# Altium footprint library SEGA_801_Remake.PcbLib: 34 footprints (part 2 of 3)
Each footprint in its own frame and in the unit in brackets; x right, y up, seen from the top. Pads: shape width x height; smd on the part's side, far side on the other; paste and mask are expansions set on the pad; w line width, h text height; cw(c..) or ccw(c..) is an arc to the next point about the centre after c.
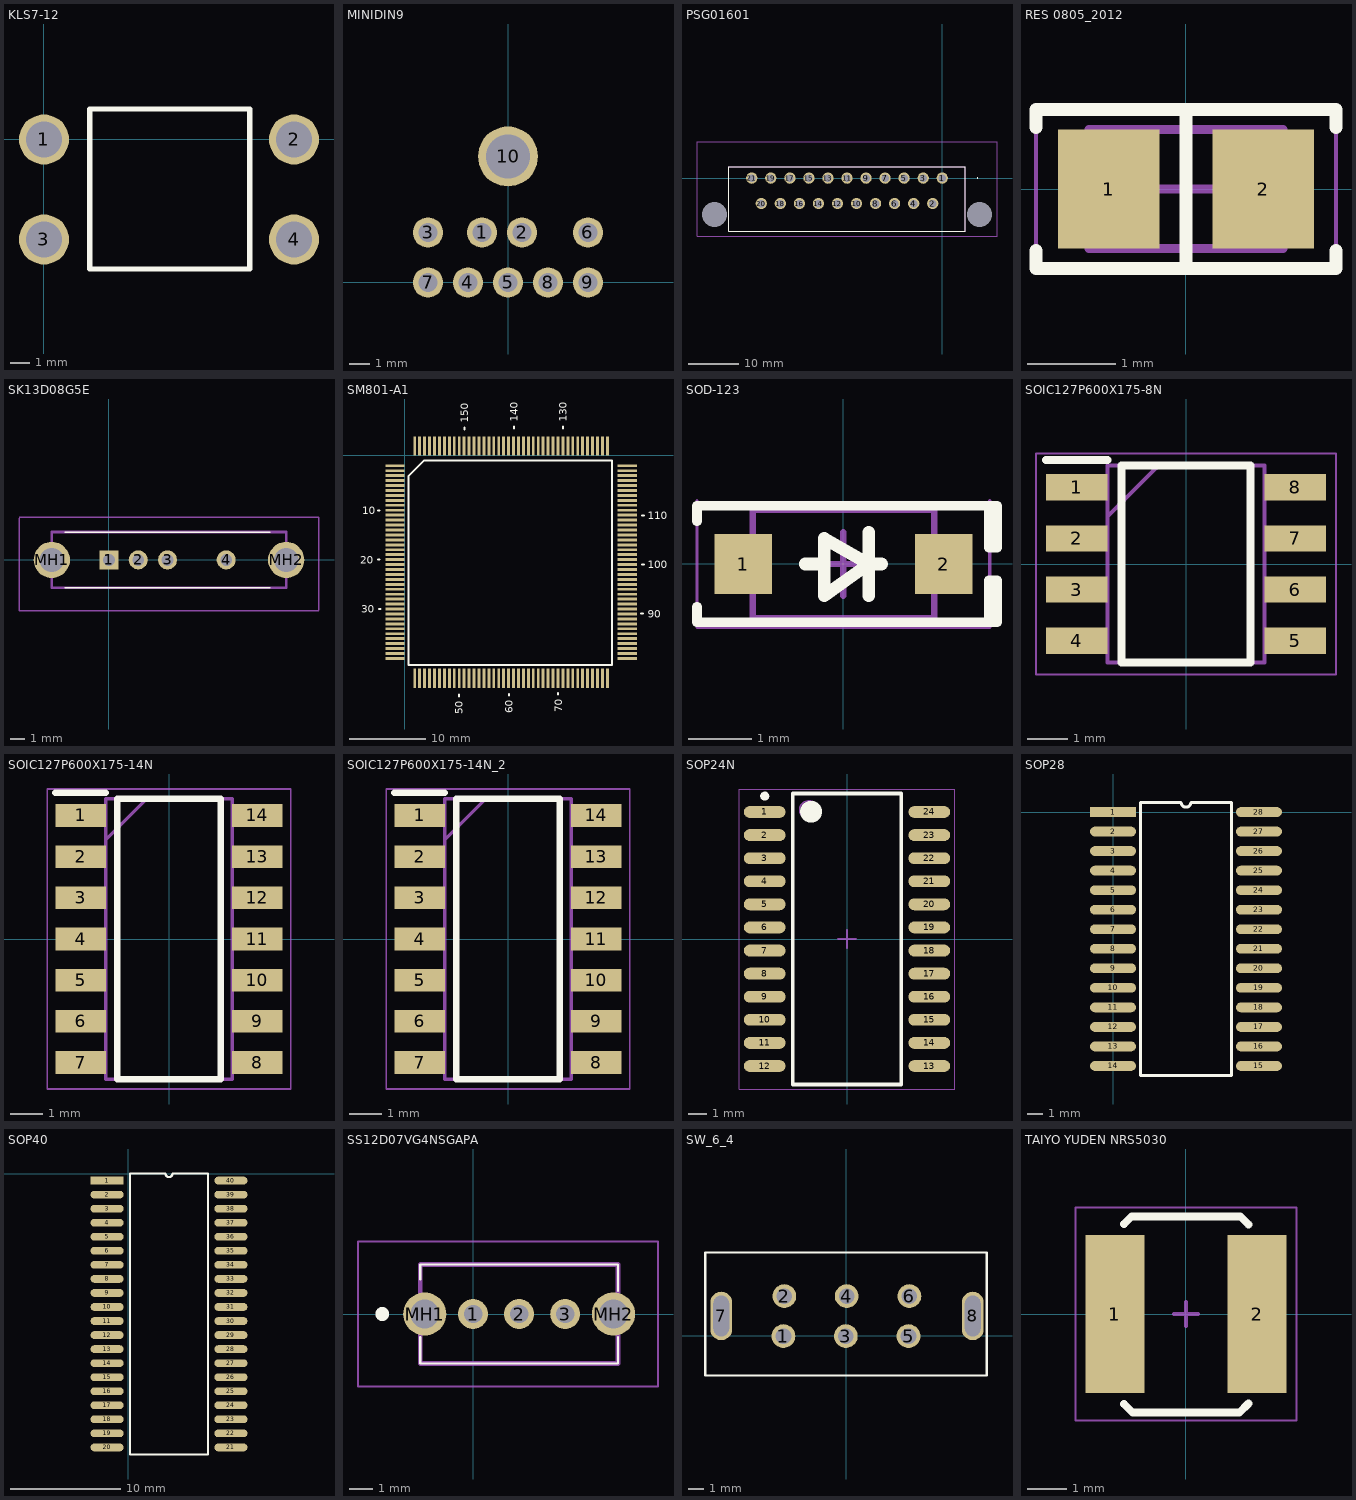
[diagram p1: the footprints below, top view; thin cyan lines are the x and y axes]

## KLS7-12 [mm]
pads (4):
  round 2.5 hole 1.8: 1(0,0) 2(12.5,0) 3(0,-5) 4(12.5,-5)
Top Overlay:
  lines w0.254: 2.286,-6.477 2.286,1.524 10.287,1.524 10.287,-6.477 2.286,-6.477

## MINIDIN9 [mm]
pads (10):
  round 1.524 hole 0.95: 1(-1.3,2.5) 2(0.7,2.5) 3(-4,2.5) 4(-2,0) 5(0,0) 6(4,2.5) 7(-4,0) 8(2,0) 9(4,0)
  round 3 hole 2.2: 10(0,6.3)
Bottom Overlay:
  lines w0.254: -7.5,-1.651 7.5,-1.651 7.5,11 -7.5,11 -7.5,-1.651

## PSG01601 [mm]
pads (23):
  round 2.25 hole 1.5: 1(0,0) 2(-1.905,-5.08) 3(-3.81,0) 4(-5.715,-5.08) 5(-7.62,0) 6(-9.525,-5.08) 7(-11.43,0) 8(-13.335,-5.08) 9(-15.24,0) 10(-17.145,-5.08) 11(-19.05,0) 12(-20.955,-5.08) 13(-22.86,0) 14(-24.765,-5.08) 15(-26.67,0) 16(-28.575,-5.08) 17(-30.48,0) 18(-32.385,-5.08) 19(-34.29,0) 20(-36.195,-5.08) 21(-38.1,0)
  round 2.5 hole 5 unplated: MH1(-45.55,-7.28) MH2(7.45,-7.28)
Top Overlay:
  lines w0.1: 7,0 cw(c7.05,0) 7.1,0 cw(c7.05,0) 7,0
  lines w0.2: -42.65,-10.6 -42.65,2.286 -26.886,2.286 -11.214,2.286 4.55,2.286 4.55,-10.6 -42.65,-10.6
Mechanical 13:
  lines w0.1: -42.65,-10.6 -42.65,2.286 -26.886,2.286 -11.214,2.286 -6.94,2.286 4.24,2.286 4.55,2.286 4.55,-10.6 -42.65,-10.6
Mechanical 15:
  lines w0.1: -49.05,-11.6 -49.05,7.25 10.95,7.25 10.95,-11.6 -49.05,-11.6
3D body "PSG01601.stp": height 16.8, standoff -5, extent -47.814,-14.31 9.968,2.54

## RES 0805_2012 [mm] "Chip Resistor, 2-Leads, Body 2.00x1.25mm, IPC Medium Density"
height 0.7
pads (2):
  rect 1.15x1.35 smd: 1(-0.875,0) 2(0.875,0)
Top Overlay:
  lines w0.15: -1.7,-0.7 -1.7,-0.9 1.7,-0.9 1.7,-0.7 ; -1.7,0.7 -1.7,0.9 1.7,0.9 1.7,0.7 ; 0,-0.9 0,0.9
Mechanical 13:
  lines w0.1: -1.1,-0.675 1.1,-0.675 1.1,0.675 -1.1,0.675 -1.1,-0.675
Mechanical 15:
  lines w0.05: -1.7,-0.95 1.7,-0.95 1.7,0.95 -1.7,0.95 -1.7,-0.95
  lines w0.1: -0.5,0 0.5,0 ; 0,-0.5 0,0.5
3D body "0805 resistor.STEP": height 0.6, standoff 0, extent -1,-0.625 1,0.625

## SK13D08G5E [mm]
pads (6):
  rect 1.3x1.3 hole 0.8: 1(0,0)
  round 1.3 hole 0.8: 2(2,0) 3(4,0) 4(8,0)
  round 2.475 hole 1.65: MH1(-3.9,0) MH2(12.1,0)
Top Overlay:
  lines w0.1: -3,-1.9 11,-1.9 ; -3,1.9 11,1.9
Mechanical 13:
  lines w0.2: -3.9,-1.9 -3.9,1.9 12.1,1.9 12.1,-1.9 -3.9,-1.9
Mechanical 15:
  lines w0.1: -6.137,2.9 14.337,2.9 14.337,-3.429 ; -6.123,2.847 -6.123,-3.455 -1.019,-3.455 9.218,-3.455 14.337,-3.455

## SM801-A1 [mil]
pads (160):
  rect 100x15 smd: 1(-50.75,-53.45) 2(-50.75,-79.05) 3(-50.75,-104.65) 4(-50.75,-130.25) 5(-50.75,-155.85) 6(-50.75,-181.45) 7(-50.75,-207.05) 8(-50.75,-232.65) 9(-50.75,-258.25) 10(-50.75,-283.85) 11(-50.75,-309.45) 12(-50.75,-335.05) 13(-50.75,-360.65) 14(-50.75,-386.25) 15(-50.75,-411.85) 16(-50.75,-437.45) 17(-50.75,-463.05) 18(-50.75,-488.65) 19(-50.75,-514.25) 20(-50.75,-539.85) 21(-50.75,-565.45) 22(-50.75,-591.05) 23(-50.75,-616.65) 24(-50.75,-642.25) 25(-50.75,-667.85) 26(-50.75,-693.45) 27(-50.75,-719.05) 28(-50.75,-744.65) 29(-50.75,-770.25) 30(-50.75,-795.85) 31(-50.75,-821.45) 32(-50.75,-847.05) 33(-50.75,-872.65) 34(-50.75,-898.25) 35(-50.75,-923.85) 36(-50.75,-949.45) 37(-50.75,-975.05) 38(-50.75,-1000.65) 39(-50.75,-1026.25) 40(-50.75,-1051.85) 81(1152.45,-1051.85) 82(1152.45,-1026.25) 83(1152.45,-1000.65) 84(1152.45,-975.05) 85(1152.45,-949.45) 86(1152.45,-923.85) 87(1152.45,-898.25) 88(1152.45,-872.65) 89(1152.45,-847.05) 90(1152.45,-821.45) 91(1152.45,-795.85) 92(1152.45,-770.25) 93(1152.45,-744.65) 94(1152.45,-719.05) 95(1152.45,-693.45) 96(1152.45,-667.85) 97(1152.45,-642.25) 98(1152.45,-616.65) 99(1152.45,-591.05) 100(1152.45,-565.45) 101(1152.45,-539.85) 102(1152.45,-514.25) 103(1152.45,-488.65) 104(1152.45,-463.05) 105(1152.45,-437.45) 106(1152.45,-411.85) 107(1152.45,-386.25) 108(1152.45,-360.65) 109(1152.45,-335.05) 110(1152.45,-309.45) 111(1152.45,-283.85) 112(1152.45,-258.25) 113(1152.45,-232.65) 114(1152.45,-207.05) 115(1152.45,-181.45) 116(1152.45,-155.85) 117(1152.45,-130.25) 118(1152.45,-104.65) 119(1152.45,-79.05) 120(1152.45,-53.45)
  rect 15x100 smd: 41(51.65,-1154.25) 42(77.25,-1154.25) 43(102.85,-1154.25) 44(128.45,-1154.25) 45(154.05,-1154.25) 46(179.65,-1154.25) 47(205.25,-1154.25) 48(230.85,-1154.25) 49(256.45,-1154.25) 50(282.05,-1154.25) 51(307.65,-1154.25) 52(333.25,-1154.25) 53(358.85,-1154.25) 54(384.45,-1154.25) 55(410.05,-1154.25) 56(435.65,-1154.25) 57(461.25,-1154.25) 58(486.85,-1154.25) 59(512.45,-1154.25) 60(538.05,-1154.25) 61(563.65,-1154.25) 62(589.25,-1154.25) 63(614.85,-1154.25) 64(640.45,-1154.25) 65(666.05,-1154.25) 66(691.65,-1154.25) 67(717.25,-1154.25) 68(742.85,-1154.25) 69(768.45,-1154.25) 70(794.05,-1154.25) 71(819.65,-1154.25) 72(845.25,-1154.25) 73(870.85,-1154.25) 74(896.45,-1154.25) 75(922.05,-1154.25) 76(947.65,-1154.25) 77(973.25,-1154.25) 78(998.85,-1154.25) 79(1024.45,-1154.25) 80(1050.05,-1154.25) 121(1050.05,48.95) 122(1024.45,48.95) 123(998.85,48.95) 124(973.25,48.95) 125(947.65,48.95) 126(922.05,48.95) 127(896.45,48.95) 128(870.85,48.95) 129(845.25,48.95) 130(819.65,48.95) 131(794.05,48.95) 132(768.45,48.95) 133(742.85,48.95) 134(717.25,48.95) 135(691.65,48.95) 136(666.05,48.95) 137(640.45,48.95) 138(614.85,48.95) 139(589.25,48.95) 140(563.65,48.95) 141(538.05,48.95) 142(512.45,48.95) 143(486.85,48.95) 144(461.25,48.95) 145(435.65,48.95) 146(410.05,48.95) 147(384.45,48.95) 148(358.85,48.95) 149(333.25,48.95) 150(307.65,48.95) 151(282.05,48.95) 152(256.45,48.95) 153(230.85,48.95) 154(205.25,48.95) 155(179.65,48.95) 156(154.05,48.95) 157(128.45,48.95) 158(102.85,48.95) 159(77.25,48.95) 160(51.65,48.95)
Top Overlay:
  lines w10: -140,-540 -130,-540 ; -140,-285 -130,-285 ; -135,-795 -125,-795 ; 280,-1250 280,-1240 ; 310,135 310,145 ; 540,-1245 540,-1235 ; 565,140 565,150 ; 795,-1240 795,-1230 ; 820,140 820,150 ; 1225,-820 1235,-820 ; 1230,-565 1240,-565 ; 1230,-310 1240,-310 ; 20,-1085 20,-105 100,-25 1075,-25 1075,-1085 20,-1085
  text "150" at 330,170 h40
  text "140" at 585,175 h40
  text "130" at 840,175 h40
  text "110" at 1260,-330 h40
  text "100" at 1260,-585 h40
  text "90" at 1260,-840 h40
  text "70" at 815,-1330 h40
  text "60" at 560,-1335 h40
  text "50" at 300,-1340 h40
  text "30" at -225,-815 h40
  text "20" at -230,-560 h40
  text "10" at -220,-305 h40

## SOD-123 [mm] "SOD, 2-Leads, Body 1.55x3.70mm, IPC Medium Density"
height 1.35
pads (2):
  rect 0.9x0.95 smd: 1(-1.575,0) 2(1.575,0)
Top Overlay:
  lines w0.15: -2.3,-0.675 -2.3,-0.916 2.286,-0.916 ; -2.3,0.675 -2.3,0.916 2.286,0.916 ; 2.286,-0.916 2.286,-0.254 2.413,-0.254 2.413,-0.916 2.286,-0.916 ; 2.286,0.916 2.413,0.916 2.413,0.254 2.286,0.254 2.286,0.916
  lines w0.2: -0.6,0 -0.3,0 ; 0.4,-0.5 0.4,0.5 ; 0.6,0 0.4,0 ; 0.4,0 -0.3,-0.5 -0.3,0.4 0.4,0
Mechanical 13:
  lines w0.1: -1.425,-0.85 1.425,-0.85 1.425,0.85 -1.425,0.85 -1.425,-0.85
Mechanical 15:
  lines w0.05: -2.3,0.9 2.3,0.9 ; -2.3,1 -2.3,-1 2.3,-1 2.3,1
  lines w0.1: -0.5,0 0.5,0 ; 0,-0.5 0,0.5
3D body "SOD-123.STEP": height 1.35, standoff 0, extent -1.864,-0.775 1.864,0.775

## SOIC127P600X175-8N [mm]
pads (8):
  rect 1.525x0.65 smd: 1(-2.712,1.905) 2(-2.712,0.635) 3(-2.712,-0.635) 4(-2.712,-1.905) 5(2.712,-1.905) 6(2.712,-0.635) 7(2.712,0.635) 8(2.712,1.905)
Top Overlay:
  lines w0.2: -3.475,2.58 -1.95,2.58 ; -1.6,-2.45 1.6,-2.45 1.6,2.45 -1.6,2.45 -1.6,-2.45
Mechanical 13:
  lines w0.1: -1.95,1.18 -0.68,2.45 ; -1.95,-2.45 1.95,-2.45 1.95,2.45 -1.95,2.45 -1.95,-2.45
Mechanical 15:
  lines w0.05: -3.725,-2.75 3.725,-2.75 3.725,2.75 -3.725,2.75 -3.725,-2.75
3D body "NE555DR.stp": height 1.75, standoff 0, extent -3,-2.45 3,2.45

## SOIC127P600X175-14N [mm]
pads (14):
  rect 1.55x0.7 smd: 1(-2.725,3.81) 2(-2.725,2.54) 3(-2.725,1.27) 4(-2.725,0) 5(-2.725,-1.27) 6(-2.725,-2.54) 7(-2.725,-3.81) 8(2.725,-3.81) 9(2.725,-2.54) 10(2.725,-1.27) 11(2.725,0) 12(2.725,1.27) 13(2.725,2.54) 14(2.725,3.81)
Top Overlay:
  lines w0.2: -3.5,4.51 -1.95,4.51 ; -1.6,-4.325 1.6,-4.325 1.6,4.325 -1.6,4.325 -1.6,-4.325
Mechanical 13:
  lines w0.1: -1.95,3.055 -0.68,4.325 ; -1.95,-4.325 1.95,-4.325 1.95,4.325 -1.95,4.325 -1.95,-4.325
Mechanical 15:
  lines w0.05: -3.75,-4.625 3.75,-4.625 3.75,4.625 -3.75,4.625 -3.75,-4.625
3D body "74HC04D,652.stp": height 1.56, standoff 0, extent -3,-4.312 3,4.338

## SOIC127P600X175-14N_2 [mm]
pads (14):
  rect 1.55x0.7 smd: 1(-2.725,3.81) 2(-2.725,2.54) 3(-2.725,1.27) 4(-2.725,0) 5(-2.725,-1.27) 6(-2.725,-2.54) 7(-2.725,-3.81) 8(2.725,-3.81) 9(2.725,-2.54) 10(2.725,-1.27) 11(2.725,0) 12(2.725,1.27) 13(2.725,2.54) 14(2.725,3.81)
Top Overlay:
  lines w0.2: -3.5,4.51 -1.95,4.51 ; -1.6,-4.325 -1.6,4.325 1.6,4.325 1.6,-4.325 -1.6,-4.325
Mechanical 13:
  lines w0.1: -1.95,3.055 -0.68,4.325 ; -1.95,-4.325 -1.95,4.325 1.95,4.325 1.95,-4.325 -1.95,-4.325
Mechanical 15:
  lines w0.05: -3.75,-4.625 -3.75,4.625 3.75,4.625 3.75,-4.625 -3.75,-4.625
3D body "74HC04D,652.stp": height 1.56, standoff 0, extent -3,-4.312 3,4.338

## SOP24N [mm] "SOP, 24-Leads, Body 15,90x5,65mm, Pitch 1,27mm, IPC Medium Density"
height 2.65
pads (24):
  oval 2.3x0.65 smd: 1(-4.525,6.985) 2(-4.525,5.715) 3(-4.525,4.445) 4(-4.525,3.175) 5(-4.525,1.905) 6(-4.525,0.635) 7(-4.525,-0.635) 8(-4.525,-1.905) 9(-4.525,-3.175) 10(-4.525,-4.445) 11(-4.525,-5.715) 12(-4.525,-6.985) 13(4.525,-6.985) 14(4.525,-5.715) 15(4.525,-4.445) 16(4.525,-3.175) 17(4.525,-1.905) 18(4.525,-0.635) 19(4.525,0.635) 20(4.525,1.905) 21(4.525,3.175) 22(4.525,4.445) 23(4.525,5.715) 24(4.525,6.985)
Top Overlay:
  circle w0.25: c-4.525,7.86 r0.125
  circle w0.6: c-1.975,7 r0.3
  lines w0.2: -2.975,-8 -2.975,8 2.975,8 2.975,-8 -2.975,-8
Mechanical 13:
  circle w0.1: c-2.1,7.1 r0.5
  lines w0.1: -3,-8 -3,8 3,8 3,-8 -3,-8
Mechanical 15:
  lines w0.05: -5.925,-8.25 -5.925,8.25 5.925,8.25 5.925,-8.25 -5.925,-8.25
  lines w0.1: -0.5,0 0.5,0 ; 0,-0.5 0,0.5
3D body: height 2.65, standoff 0.1, extent -3,-8 3,8

## SOP28 [mm]
pads (28):
  rect 3x0.64 smd: 1(0,0)
  oval 3x0.64 smd: 2(0,-1.27) 3(0,-2.54) 4(0,-3.81) 5(0,-5.08) 6(0,-6.35) 7(0,-7.62) 8(0,-8.89) 9(0,-10.16) 10(0,-11.43) 11(0,-12.7) 12(0,-13.97) 13(0,-15.24) 14(0,-16.51) 15(9.49,-16.51) 16(9.49,-15.24) 17(9.49,-13.97) 18(9.49,-12.7) 19(9.49,-11.43) 20(9.49,-10.16) 21(9.49,-8.89) 22(9.49,-7.62) 23(9.49,-6.35) 24(9.49,-5.08) 25(9.49,-3.81) 26(9.49,-2.54) 27(9.49,-1.27) 28(9.49,0)
Top Overlay:
  lines w0.2: 1.785,-17.145 7.705,-17.145 7.705,0.635 5.062,0.635 cw(c4.745,0.635) 4.427,0.635 1.785,0.635 1.785,-17.145

## SOP40 [mm]
pads (40):
  rect 3x0.7 smd: 1(-1.905,-0.635)
  oval 3x0.7 smd: 2(-1.905,-1.905) 3(-1.905,-3.175) 4(-1.905,-4.445) 5(-1.905,-5.715) 6(-1.905,-6.985) 7(-1.905,-8.255) 8(-1.905,-9.525) 9(-1.905,-10.795) 10(-1.905,-12.065) 11(-1.905,-13.335) 12(-1.905,-14.605) 13(-1.905,-15.875) 14(-1.905,-17.145) 15(-1.905,-18.415) 16(-1.905,-19.685) 17(-1.905,-20.955) 18(-1.905,-22.225) 19(-1.905,-23.495) 20(-1.905,-24.765) 21(9.295,-24.765) 22(9.295,-23.495) 23(9.295,-22.225) 24(9.295,-20.955) 25(9.295,-19.685) 26(9.295,-18.415) 27(9.295,-17.145) 28(9.295,-15.875) 29(9.295,-14.605) 30(9.295,-13.335) 31(9.295,-12.065) 32(9.295,-10.795) 33(9.295,-9.525) 34(9.295,-8.255) 35(9.295,-6.985) 36(9.295,-5.715) 37(9.295,-4.445) 38(9.295,-3.175) 39(9.295,-1.905) 40(9.295,-0.635)
Top Overlay:
  lines w0.2: 0.18,-25.4 0.18,0 3.377,0 ccw(c3.695,0) 4.012,0 7.21,0 7.21,-25.4 0.18,-25.4

## SS12D07VG4NSGAPA [mm]
pads (5):
  round 1.3 hole 0.8: 1(0,0) 2(2,0) 3(4,0)
  round 1.875 hole 1.25: MH1(-2.1,0) MH2(6.1,0)
Top Overlay:
  lines w0.1: -2.3,-1 -2.3,-2 -2.3,-2.15 6.3,-2.15 6.3,-1 ; -2.3,1.5 -2.3,2.15 6.3,2.15 6.3,1
  lines w0.5: -4,0 ccw(c-3.95,0) -3.9,0 ccw(c-3.95,0) -4,0
Mechanical 13:
  lines w0.2: -2.3,-2.15 6.3,-2.15 6.3,2.15 -2.3,2.15 -2.3,-2.15
Mechanical 15:
  lines w0.1: -5,-3.15 8.037,-3.15 8.037,3.15 -5,3.15 -5,-3.15
3D body "SS12D07VG4NSGAPA.stp": height 7.1, standoff -5, extent -2.621,-2.15 6.625,2.15

## SW_6_4 [mil]
pads (8):
  round 60 hole 39.37: 1(-157.9,-0.94) 2(-155.69,100) 3(-0.38,-0.94) 4(1.83,100) 5(157.79,-0.94) 6(160,100)
  oval 55.37x122.36 hole 103 slot 39.37 at 0 deg: 7(-315,50) 8(320,50)
Top Overlay:
  lines w6: -355,-100.28 355,-100.28 355,195 355,210 -355,210 -355,-90 -355,-100.28

## TAIYO YUDEN NRS5030 [mm] "Inductor, 2-Leads,Taiyo Yuden, NRS5030T4R7MMGJV"
height 3
pads (2):
  rect 1.5x4 smd: 1(-1.8,0) 2(1.8,0)
Top Overlay:
  lines w0.2: -1.575,-2.275 -1.35,-2.5 1.35,-2.5 1.581,-2.269 ; -1.575,2.275 -1.375,2.475 1.375,2.475 1.587,2.262
Mechanical 15:
  lines w0.05: -2.8,-2.7 -2.8,2.7 2.8,2.7 2.8,-2.7 -2.8,-2.7
  lines w0.1: -0.3,0 0.3,0 ; 0,-0.3 0,0.3
3D body "Taiyo Yuden - NRS5030.step": height 3, standoff 0, extent -2.5,-2.5 2.5,2.5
